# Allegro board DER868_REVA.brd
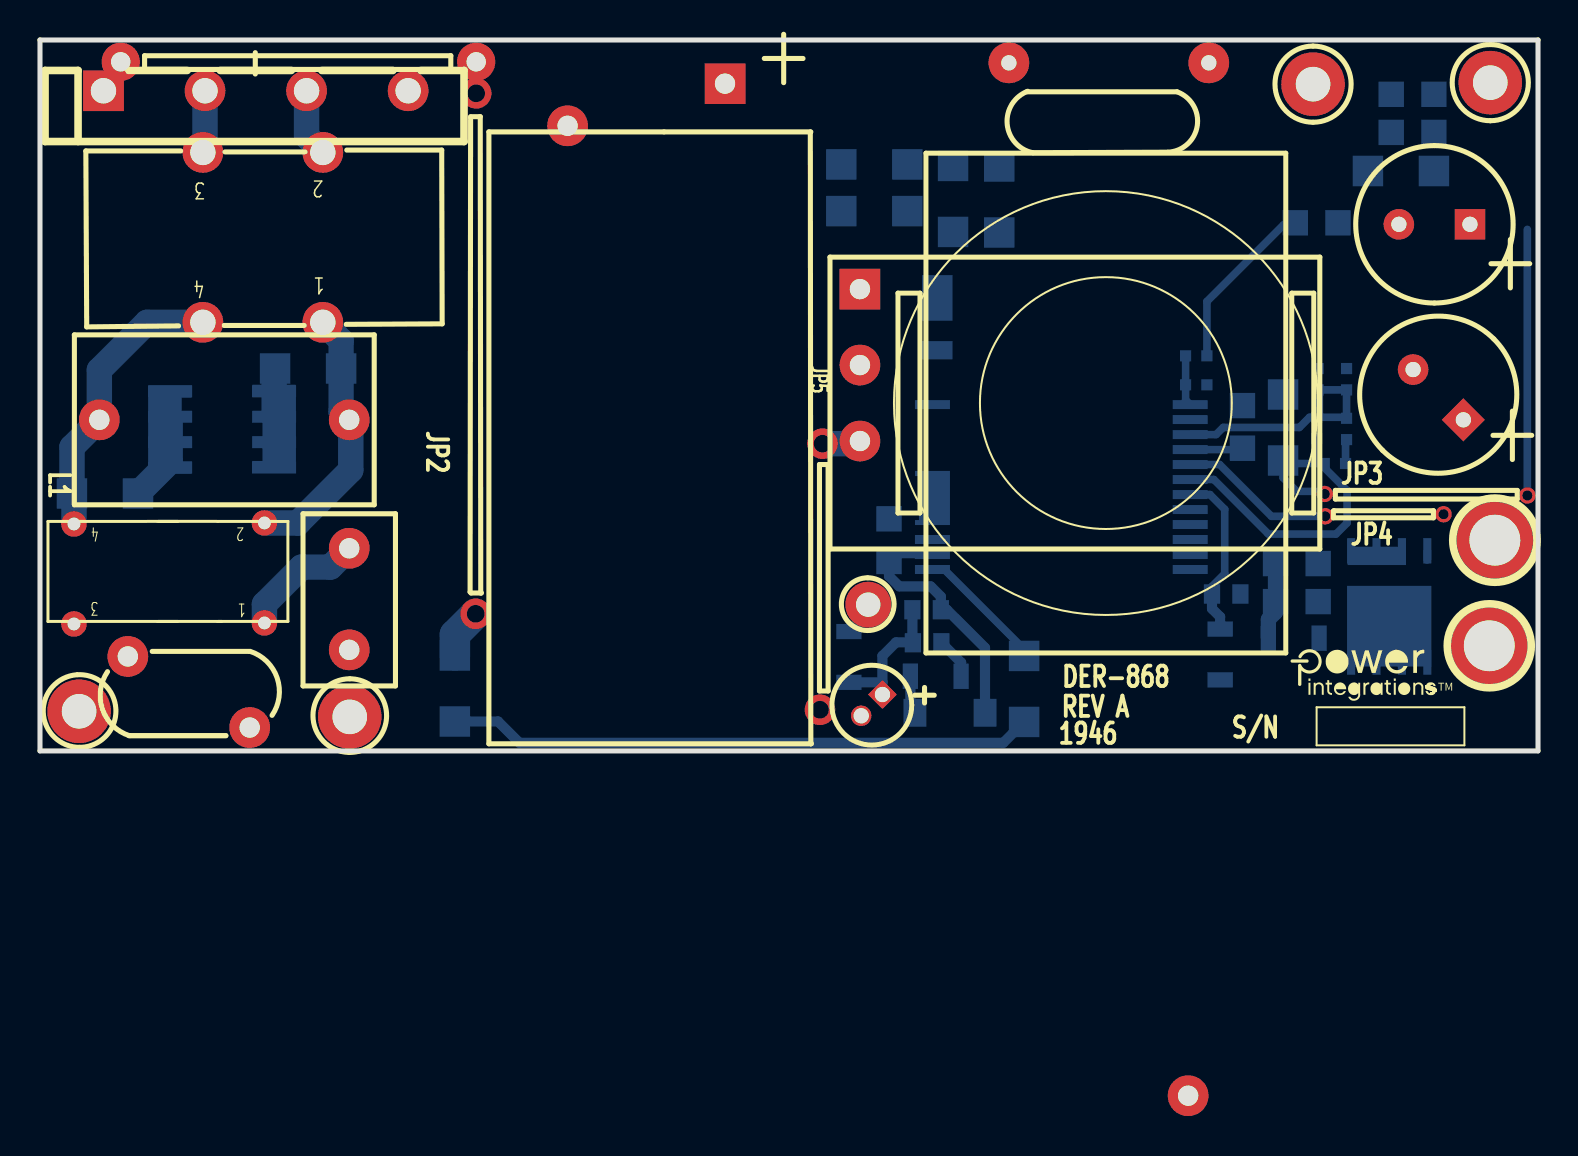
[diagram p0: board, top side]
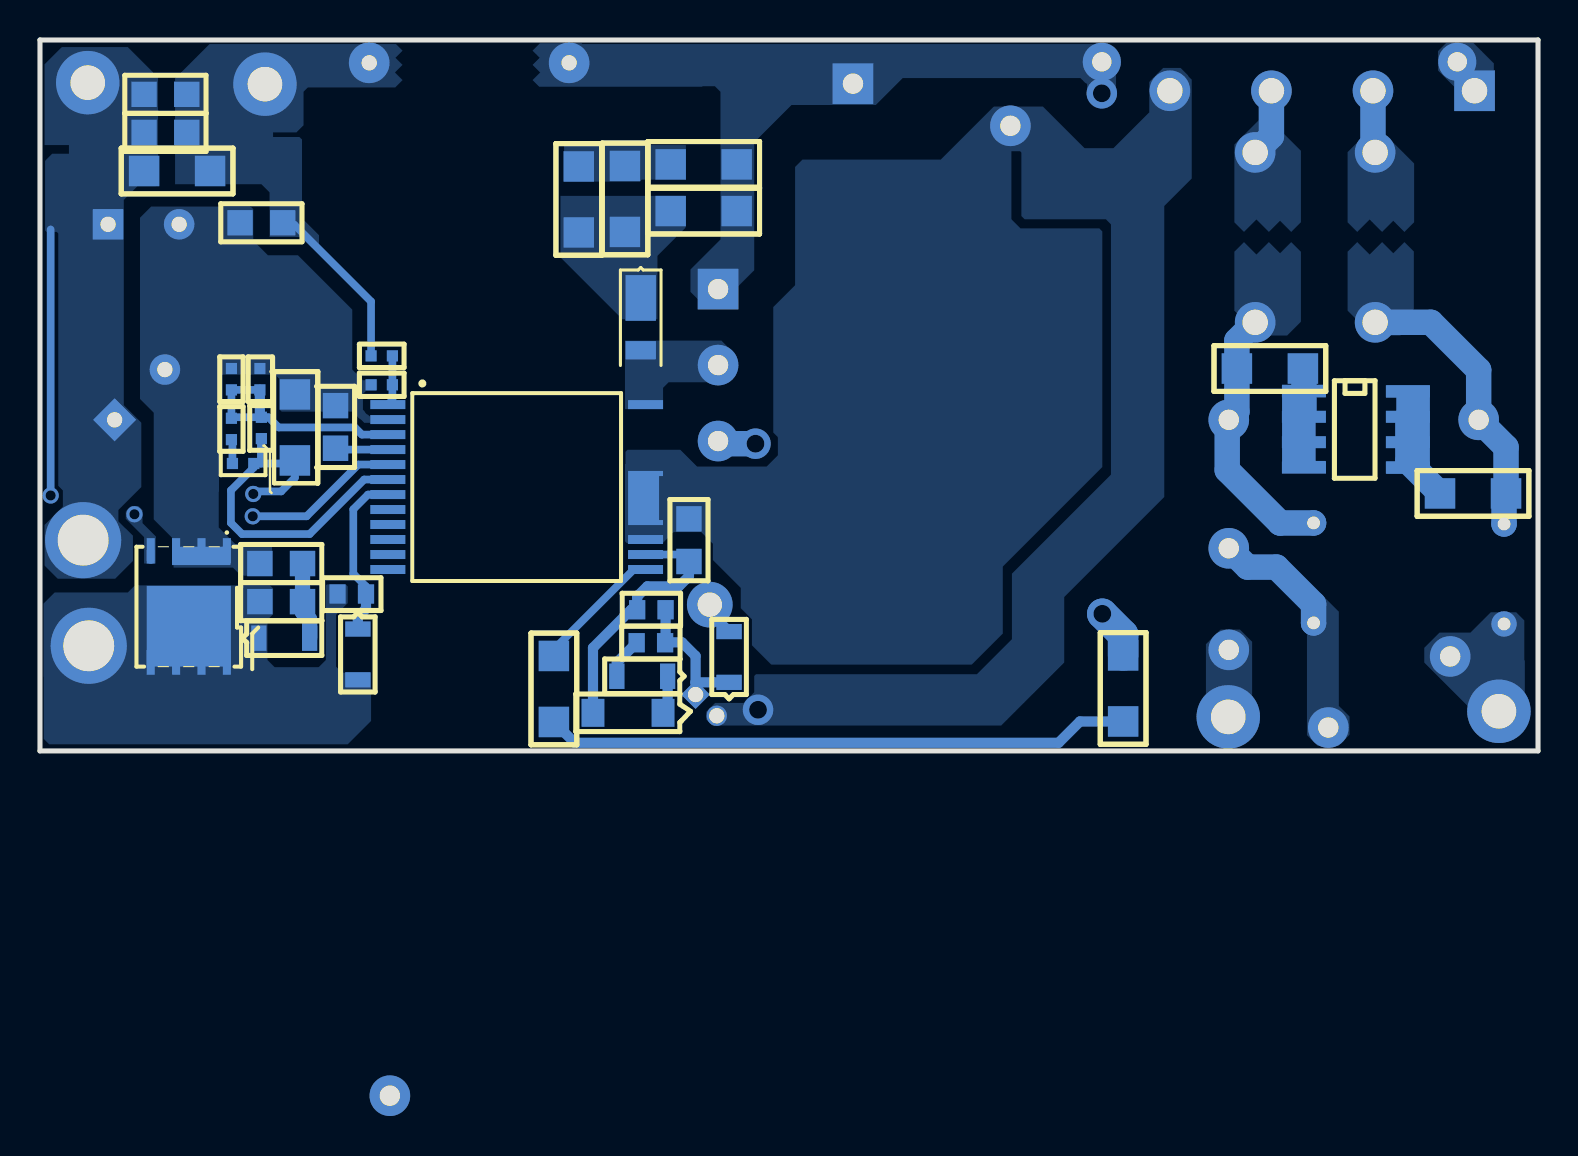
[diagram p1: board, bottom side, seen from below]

Outline 74.93 x 35.56 mm; copper layers: TOP, BOTTOM. Coordinates in mm from the lower left corner of the outline.
Outline path: 0,35.56 74.93,35.56 74.93,0 0,0 0,35.56

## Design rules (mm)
constraint set DEFAULT: min track width 0.508

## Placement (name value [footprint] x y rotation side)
BR1  GBL06  [PIDAXBRIDGEGBL06]  3.17 33.02 0 top
C1  330 nF  [PINP_XCAPRAD15X8P5X14HD040]  15.47 16.56 180 top
C2  100 uF  [PIPOLCAPCLYD630LS300040]  34.26 33.38 180 bottom
C3  680 pF  [PINPCAPRAD394X275394030]  48.46 34.42 0 top
C4  2.2 nF  [PISMC1206]  40.08 29.34 0 bottom
C5  6.8 uF  [PIPOLCAP4P0X11P0XLS1P5D030]  42.14 2.82 225 top
C6  4.7 uF  [PISMC0805]  42.47 9.47 90 bottom
C7  3.3 nF  [PISMC0805]  61.8 9.37 0 bottom
C8  560 uF  [PIPOLCAPCLYD320LS140030]  71.2 16.56 135 top
C9  560 uF  [PIPOLCAPCLYD320LS140030]  71.53 26.34 180 top
C10  2.2 uF  [PISMC0805]  60.15 17.27 270 bottom
C11  2.2 uF  [PISMC1206]  62.18 17.83 270 bottom
C12  1000 pF  [PISMR0402]  58.37 18.31 180 bottom
C13  330 pF  [PISMC0402]  63.93 18.06 90 bottom
C14  10 nF  [PISMR0402]  65.35 15.57 90 bottom
C15  47 uF  [PISMC1206]  69.72 29.01 180 bottom
C16  1 uF  [PISMC0805]  69.72 30.94 180 bottom
C17  DNP  [PISMC0805]  69.72 32.84 180 bottom
D1  DFLR1800-7  [PISMDDFLR120012]  44.88 22.68 90 bottom
D2  BAV3004WS-7  [PISMSOD323]  40.46 3.43 90 bottom
D3  BAV19WS  [PISMSOD323]  43.54 3.73 0 bottom
D4  BAV19WS  [PISMSOD323]  63.98 5.64 180 bottom
D5  BAV21WS-7-F  [PISMSOD323]  59.03 6.1 270 bottom
F1  3.15 A  [PI_RST_MICROFUSE]  15.47 5.05 90 top
FL1  Hole_100mils  [PI_HOLE_100MIL]  72.77 10.54 0 top
FL2  Hole_100mils  [PI_HOLE_100MIL]  72.49 5.26 0 top
FL3  Hole_50mils  [PI_HOLE_50MIL]  41.43 7.32 0 top
J1  PCB Terminal 18 AWG  [PI_HOLE_18AWG]  15.49 1.68 0 top
J2  PCB Terminal 18 AWG  [PI_HOLE_18AWG]  1.96 1.96 0 top
J3  PCB Terminal 18 AWG  [PI_HOLE_18AWG]  72.54 33.4 0 top
J4  PCB Terminal 18 AWG  [PI_HOLE_18AWG]  63.68 33.32 0 top
JP1  J  [PI_JUMPER700]  4.04 34.47 0 top
L1  250 uH  [PI_TOROID_CMC4P_V_275UH]  7.9 6.48 180 top
L2  04291-T231  [PI_CMC_18MH_SUMIDA]  14.15 21.44 180 top
NOREF  -  []  62 4.98 0 top
NOREF#2  -  []  -231.19 -144.73 0 top
NOREF#3  -  []  0 35.56 0 top
NOREF#4  -  []  -153.38 54.28 0 top
NOREF#5  -  []  0.03 0.03 90 top
Q1  AON6220  [PISMPQFN5X6B]  65.58 10.01 0 bottom
R1  1 M  [PISMR1206]  15.06 19.13 180 bottom
R2  1 M  [PISMR1206]  4.9 12.88 180 bottom
R3  2.00 M  [PISMR1206]  20.75 1.47 90 bottom
R4  1.80 M  [PISMR1206]  49.23 4.75 270 bottom
R5  39  [PISMR1206]  47.98 25.93 90 bottom
R6  39  [PISMR1206]  45.67 25.96 90 bottom
R7  300 k  [PISMR1206]  40.08 27 0 bottom
R8  3 k  [PISMR0603]  43.64 7.06 0 bottom
R9  47  [PISMR0603]  43.66 5.41 0 bottom
R11  3  [PISMR0805]  61.8 7.47 0 bottom
R12  47  [PISMR0603]  60.05 7.85 180 bottom
R13  0.0  [PISMR0402]  57.3 19.76 0 bottom
R14  0.006  [PISMR0805]  64.92 26.42 180 bottom
R15  169.0 k  [PISMR0402]  63.86 15.62 90 bottom
R16  19.1 k  [PISMR0402]  65.35 19.13 270 bottom
R17  82.0 k  [PISMR0402]  64.24 14.38 0 bottom
RV1  DNP  [PIDISC350X160LS210X140040]  10.49 1.17 180 top
T1  EQ25  [PI_BOBBIN_EQ-2515P5_4P]  53.31 17.4 0 top
U1  INN3679C-H606  [PI_IC_INSOP_24D]  57.53 17.32 180 bottom
U2  CAP200DG  [PI_IC_SMD_SO8_CAPZERO]  11.71 17.98 270 bottom
VR1  MMSZ5242B-7-F  [PI_SM_SOD-123_12]  43.76 1.91 0 bottom

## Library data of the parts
BR1 = DISCRETE BRIDGE_+~~-: room: 2
C1 = CAP NP: alternate symbols: (pinp_xcaprad15x8p5x14Hd040H); room: 2
C2 = CAP POL: alternate symbols: (pipolcapclyd630ls3000401120h); room: 2
C3 = CAP NP: alternate symbols: (pinpycaprad500x220ls400040); room: 2
C4 C10 = CAP NP_0: room: 2
C5 = CAP POL: alternate symbols: (pipolcap4p0x11p0xls1p5d030h); room: 2
C6 C7 C11 C14-C17 = CAP NP: room: 2
C8 C9 = CAP POL: alternate symbols: (pipolcapclyd320ls140030430h); room: 2
C12 C13 = CAP NP: alternate symbols: (pismr0402_1); room: 2
D1-D4 = DIODE: room: 2
D5 = DIODE
F1 = FUSE: alternate symbols: (pirstmicrofusehoz); room: 2
FL1-FL3 = FlyingLead: room: 2
J1-J4 = TERM_1Pin: room: 2
JP1 = JUMPER_1: room: 2
L1 = TORRID 4P_12_34: alternate symbols: (pi_toroid_CMC4p_V,pi_toroid_CMC4p_V_275uH); room: 2
L2 = TORRID 4P_12_43a: room: 2
Q1 = FET_N_SGD_123_4_5678: room: 2
R1-R9 R11-R13 R15-R17 = R: room: 2
R14 = R
RV1 = VARISTOR: alternate symbols: (pi_disc_354x220_ls220x10_040_h); room: 2
T1 = BEQ2506_4P
U1 = Inno3EP_0
U2 = CAPZero: room: 2
VR1 = DIODE_ZENER: room: 2

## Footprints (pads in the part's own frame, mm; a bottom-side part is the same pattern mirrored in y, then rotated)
PI_BOBBIN_EQ-2515P5_4P
  rect 2.032x2.032 hole 1.016: 1(-12.301,5.7)
  round 2.032 hole 1.016: 2(-12.301,1.9) 3(-12.301,-1.9) 4(4.115,-34.646)
PI_CMC_18MH_SUMIDA
  round 2.032 hole 1.27: 1(0,0) 2(0,-8.499) 3(5.999,-8.499) 4(5.999,0)
PI_HOLE_18AWG
  round 3.175 hole 1.727: 1(0,0.025)
PI_HOLE_50MIL
  round 2.286 hole 1.219: 1(0,0)
PI_HOLE_100MIL
  round 3.81 hole 2.54: 1(0,0)
PI_IC_INSOP_24D
  rect 1.75x0.45 smd: 1(0,0) 2(0,-0.749) 3(0,-1.501) 4(0,-2.25) 5(0,-3) 6(0,-3.749) 7(0,-4.501) 8(0,-5.25) 9(0,-5.999) 10(0,-6.749) 11(0,-7.501) 12(0,-8.25) 13(12.89,-8.25) 14(12.89,-7.501) 15(12.89,-6.749) 24(12.89,0)
  custom 0.437x0.437 smd: 16(12.89,-4.671)
PI_IC_SMD_SO8_CAPZERO
  rect 0.599x2.2 smd: 1(0,0) 2(1.27,0) 3(2.54,0) 4(3.81,0) 5(3.81,5.199) 6(2.54,5.199) 7(1.27,5.199) 8(0,5.199)
PI_JUMPER700
  round 1.905 hole 0.965: 1(0,0) 2(17.78,0)
PI_RST_MICROFUSE
  round 2.032 hole 1.016: 1(0,0) 2(5.08,0)
PI_SM_SOD-123_12
  rect 1.143x1.397 smd: 1(0,0) 2(3.505,0)
PI_TOROID_CMC4P_V_275UH
  round 1.27 hole 0.635: 1(-3.327,0.076) 2(-3.327,-4.925) 3(6.2,0.127) 4(6.2,-4.874)
PIDAXBRIDGEGBL06
  rect 2.032x2.032 hole 1.27: 1(0,0)
  round 2.032 hole 1.27: 2(5.08,0) 3(10.16,0) 4(15.24,0)
PIDISC350X160LS210X140040
  round 2.032 hole 1.016: 1(0,0) 2(6.096,-3.556)
PINP_XCAPRAD15X8P5X14HD040
  round 2.032 hole 1.016: 1(0,0) 2(12.499,0)
PINPCAPRAD394X275394030
  round 2.032 hole 0.762: 1(0,0) 2(10,0)
PIPOLCAP4P0X11P0XLS1P5D030
  rect 1.016x1.016 hole 0.762: 1(0,0)
  round 1.016 hole 0.762: 2(1.501,0)
PIPOLCAPCLYD320LS140030
  rect 1.524x1.524 hole 0.762: 1(0,0)
  round 1.524 hole 0.762: 2(3.556,0)
PIPOLCAPCLYD630LS300040
  rect 2.032x2.032 hole 1.016: 1(0,0)
  round 2.032 hole 1.016: 2(7.874,-2.108)
PISMC0402
  rect 0.559x0.559 smd: 1(0,0) 2(1.067,0)
PISMC0805
  rect 1.27x1.27 smd: 1(0,0) 2(2.134,0)
PISMC1206
  rect 1.524x1.524 smd: 1(0,0) 2(3.302,0)
PISMDDFLR120012
  rect 2.286x1.524 smd: 1(-0.025,0)
  rect 0.914x1.524 smd: 2(-2.642,0)
PISMPQFN5X6B
  rect 0.406x1.27 smd: 1(0,0) 2(1.27,0) 3(2.54,0) 4(3.81,0)
  rect 0.406x1.219 smd: 5(3.81,5.588) 6(2.54,5.588) 7(1.27,5.588) 8(0,5.588)
PISMR0402
  rect 0.559x0.559 smd: 1(0,0) 2(1.067,0)
PISMR0603
  rect 0.813x0.965 smd: 1(0,0) 2(1.422,0)
PISMR0805
  rect 1.27x1.27 smd: 1(0,0) 2(2.134,0)
PISMR1206
  rect 1.524x1.524 smd: 1(0,0) 2(3.302,0)
PISMSOD323
  rect 0.762x1.27 smd: 1(0,0) 2(2.54,0)

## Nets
GND: C7.2 C8.2 C9.2 C10.1 C11.1 C12.1 C13.2 Q1.1 Q1.2 Q1.3(S3) R14.1 R16.1 U1.2
GND_SIGNAL: C3.2 C15.2 C16.2 C17.2 J4.1 R13.2 R14.2
VBUS_IN: C8.1 C9.1 C11.2 C15.1 C16.1 C17.1 FL1.1 J3.1 R15.1 R17.1 U1.6
D: D4.1 D5.2 FL2.1 Q1.5 Q1.6 Q1.7 Q1.8 R11.2 R12.1
NC8: U1.8
NC9: U1.9
NC10: U1.10
NC11: U1.11
NC12: U1.12
V-PIN: R4.1 U1.13(VPIN)
N10479111: F1.1 J1.1
N10805923: BR1.4 C2.2 C5.2 C6.2 T1.3 U1.15 U1.16
N10806149: C6.1 R8.2 U1.14 VR1.2
N10808843: C12.2 R13.1 U1.1
N10809540: Q1.4 U1.5
N10813018: R3.1 R4.2
N10840366: C2.1 C3.1 C4.1 JP1.2 R3.2 R7.1 T1.1
N10873526: D5.1 R12.2 U1.7
N10897256: C13.1 C14.2 R15.2 R16.2 U1.3
N10950053: C5.1 D2.1 R8.1 R9.1
N10966650: D1.2 T1.2 U1.24
N11058959: BR1.1 JP1.1
N11077448: D3.2 R9.2
N11099981: C1.1 L1.2 L2.1 R1.1
N11100013: C1.2 L1.4 L2.4 R2.2
N11100021: BR1.3(AC2) L2.2
N11100037: BR1.2 L2.3
N11105885: D2.2 FL3.1
N11139529: D1.1 R5.1 R6.1 R7.2
N11139619: C4.2 R5.2 R6.2
N11156493: C7.1 D4.2 R11.1
N11376588: F1.2 L1.1 RV1.1
N11376604: J2.1 L1.3 RV1.2
N11381159: R1.2 U2.2
N11473834: D3.1 VR1.1
N11479585: C14.1 R17.2
N11508957: R2.1 U2.7
N11512145: C10.2 U1.4

Pads without a net: T1 4; U2 1 3 4 5 6 8

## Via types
v1: diameter 1.524, hole 0.889, TOP to BOTTOM, 4 vias
v2: diameter 0.813, hole 0.508, TOP to BOTTOM, 4 vias

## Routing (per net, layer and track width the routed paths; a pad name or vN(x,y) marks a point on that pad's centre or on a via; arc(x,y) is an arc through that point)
GND: length 0.3
  BOTTOM w0.381: 59.99,17.35 60.07,17.27 C10.1 ; 63.96,9.35 C7.2 ; 62.15,17.81 C11.1
GND_SIGNAL: length 8.8
  BOTTOM w0.381: R14.2 62.69,26.31 62.2,26.31 58.37,22.48 R13.2
VBUS_IN: length 32.6
  BOTTOM w0.381: 63.88,14.38 62.33,14.38 C11.2 62.18,13.67 62.86,12.98 64.11,12.98 64.24,12.85 v2(64.26,12.85) ; 63.88,14.38 63.88,15.6 R15.1 ; 63.88,14.38 R17.1 64.24,14.17 65.38,13.03 65.38,11.4 64.82,10.85 61.44,10.85 58.71,13.57 U1.6 ; 74.4,26.09 v2(74.4,12.78)
V-PIN: length 6.6
  BOTTOM w0.381: R4.1 49.15,4.83 49.15,5.16 45.23,9.07 U1.13
N10805923: length 1.9
  BOTTOM w1.27: v1(39.14,15.37) 40.88,15.37 T1.3
  vias: v1(39.01,2.06)
N10806149: length 13
  BOTTOM w0.381: C6.1 42.82,9.82 U1.14
  BOTTOM w0.508: C6.1 42.47,8.74 42.98,8.23 44.55,8.23 45.06,7.72 R8.2 45.36,7.06 47.27,5.16 VR1.2
N10808843: length 2.5
  BOTTOM w0.381: R13.1 C12.2 57.3,17.55 U1.1
N10809540: length 8.3
  BOTTOM w0.381: 69.39,9.55 Q1.4 ; U1.5 59.01,14.32 61.59,11.73 v2(64.29,11.73)
  vias: v2(70.21,11.84)
N10813018: length 29.3
  BOTTOM w0.508: R3.1 22.91,1.47 23.98,0.41 48.18,0.41 R4.2
N10840366: length 2.5
  BOTTOM w1.524: R3.2 20.75,5.82 v1(21.79,6.86)
  vias: v1(21.82,32.89)
N10873526: length 8.5
  BOTTOM w0.381: U1.7 58.52,12.82 59.26,12.09 59.26,8.86 58.62,8.23 R12.2
  BOTTOM w0.508: R12.2 58.62,7.11 59.03,6.71 D5.1
N10897256: length 12.5
  BOTTOM w0.381: C13.1 R16.2 C14.2 65.3,16.69 R15.2 63.5,16.69 62.99,16.18 59.18,16.18 58.83,15.82 U1.3
  BOTTOM w0.508: C13.1 63.93,16.76 R15.2
N10950053: length 7.1
  BOTTOM w0.508: R8.1 43.64,5.44 43.64,5.43 ; 43.64,5.43 42.82,5.43 42.14,4.75 42.14,3.43 ; 43.64,5.43 R9.1 ; 42.14,3.43 D2.1 ; 42.14,3.43 C5.1
N11077448: length 2.1
  BOTTOM w0.508: D3.2 46.08,4.42 R9.2
N11099981: length 13.4
  BOTTOM w1.27: L2.1 15.06,20.52 R1.1 15.06,16.97 C1.1 15.54,16.48 15.54,14.05 12.9,11.4 12.9,11.4 L1.2
N11100013: length 14.5
  BOTTOM w1.27: L1.4 1.7,12.78 R2.2 1.6,15.19 C1.2 2.97,19.05 5.36,21.44 L2.4
N11100021: length 3.4
  BOTTOM w1.27: L2.2 13.33,30.75 BR1.3
N11100037: length 3.1
  BOTTOM w1.27: BR1.2 8.25,30.04 L2.3
N11105885: length 2.2
  BOTTOM w0.508: 41.4,7.4 41.4,6.9 ; 41.4,6.9 41.43,6.93 FL3.1 ; 41.4,6.9 D2.2
N11156493: length 3.9
  BOTTOM w0.762: D4.2 61.44,6.58 61.8,6.93 R11.1 C7.1
N11376588: length 6.3
  BOTTOM w1.27: F1.2 14.53,9.19 13.08,9.19 11.23,7.34 L1.1
N11381159: length 2.4
  BOTTOM w1.27: U2.2 11.71,19.08 R1.2
N11473834: length 1.9
  BOTTOM w0.508: VR1.1 43.54,2.13 D3.1
N11479585: length 1.2
  BOTTOM w0.381: R17.2 65.3,15.52 C14.1
N11508957: length 4.5
  BOTTOM w1.27: R2.1 6.51,14.49 U2.7
N11512145: length 2.6
  BOTTOM w0.381: 60.15,15.14 60.08,15.07 U1.4

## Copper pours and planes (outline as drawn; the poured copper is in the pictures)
GND on BOTTOM (solid shape): 68.33,9.3 65.41,9.3 65.41,10.21 68.33,10.21
GND on BOTTOM: 65.16,10.35 65.99,11.18 65.99,12.95 65.98,12.97 65.98,18.68 65.84,18.82 63.17,18.82 62.94,18.59 62.94,17.07 62.84,16.97 59.26,16.97 59.26,16.92 58.75,16.41 56.72,16.41 56.67,16.46 56.67,16.64 56.77,16.74 58.45,16.74 58.78,17.07 58.78,17.86 58.6,18.03 58.57,18.01 58.14,18.01 58.06,18.08 58.06,18.52 58.09,18.54 58.78,18.54 59.31,19.08 59.31,22.07 62.03,24.79 63.53,24.79 64.26,25.53 64.26,27.1 64.39,27.23 69.37,27.23 69.93,26.67 69.93,17.6 69.24,16.92 69.24,11.58 68.25,10.59 68.25,9.17 65.28,9.17 64.87,8.76 63.32,8.76 63.32,10.33 63.35,10.35
GND_SIGNAL on BOTTOM: 57.12,35.36 66.45,35.36 68.12,33.68 68.17,33.68 68.17,28.35 63.86,28.35 63.45,27.94 63.45,25.7 61.85,25.7 61.34,25.2 60.97,25.2 60.97,25.79 61.82,26.64 61.82,30.58 61.95,30.71 63.27,30.71 63.27,30.94 62.1,30.94 61.75,31.29 61.75,32.97 61.53,33.19 57.16,33.19 56.79,33.55 57.18,33.93 56.79,34.32 57.15,34.67 56.79,35.03
VBUS_IN on BOTTOM: 70.05,28.24 69.14,28.24 69.02,28.36 69.02,33.69 70.54,35.2 73.84,35.2 74.7,34.34 74.7,30.3 73.48,30.3 73.48,29.87 74.32,29.87 74.68,29.51 74.68,26.04 74.6,25.96 74.09,25.96 74.02,25.88 74.02,13.26 73.79,13.03 73.79,12.22 74.7,11.3 74.7,9.27 74.04,8.61 71.17,8.61 70.28,9.5 70.28,10.77 70.64,11.13 70.65,11.13 71.01,11.48 71.01,12.05 69.86,13.2 69.86,16.42 70.74,17.3 70.74,27.56
D on BOTTOM (solid shape): 69.6,4.22 65.38,4.22 65.38,8.25 69.6,8.25
D on BOTTOM: 74.75,3.71 74.74,3.7 74.74,0.6 74.47,0.33 59.54,0.33 58.37,1.5 58.37,3.91 59.82,3.91 60.12,4.22 60.12,6.81 59.54,7.39 59.54,8.23 59.64,8.33 60.58,8.33 60.63,8.28 60.63,4.55 60.99,4.19 63.2,4.19 63.55,4.55 63.55,6.55 63.27,6.83 63.27,8.13 63.42,8.28 70.18,8.28 70.54,7.92 74.19,7.92 74.75,7.37
Net_73 on BOTTOM (solid shape): 7.59,17.68 7.09,17.68 7.09,14.48 7.59,14.48 7.59,13.87 5.41,13.87 5.41,18.29 7.59,18.29
Net_77 on BOTTOM (solid shape): 12.8,13.89 10.62,13.89 10.62,14.5 11.13,14.5 11.13,17.7 10.62,17.7 10.62,18.31 12.8,18.31
N10479111 on BOTTOM: 16.61,0.79 16.18,0.36 14.83,0.36 14.3,0.89 14.3,5.46 14.91,6.07 15.88,6.07 16.61,5.33
N10805923 on BOTTOM: 17.88,34.16 18.75,34.16 19.44,33.46 19.44,31.94 21.23,30.15 22.68,30.15 24.77,32.23 27.22,32.23 29.87,29.58 36.79,29.58 37.16,29.21 37.16,23.29 38.25,22.2 38.25,15.93 38.02,15.7 38.02,14.78 38.58,14.22 42.06,14.22 42.9,15.06 45.54,15.06 45.64,14.96 45.64,14.35 45.67,14.35 45.67,10.49 45.57,10.39 43.79,10.39 43.23,10.95 41.86,10.95 41.27,10.36 41.27,9.55 39.88,8.15 39.88,7.14 39.32,6.58 39.32,5.28 38.35,4.32 28.32,4.32 26.77,5.87 26.77,9.22 21.79,14.2 21.79,25.98 21.95,26.14 25.88,26.14 26.34,26.59 26.34,30 25.91,30 25.84,29.93 25.84,26.76 25.68,26.59 21.62,26.59 21.36,26.34 21.36,13.82 26.31,8.86 26.31,5.59 28.07,3.84 39.12,3.84 39.2,3.75 39.2,2.93 39.74,2.4 41.16,2.4 41.61,1.96 41.61,1.57 41.3,1.27 26.85,1.27 23.7,4.42 23.7,7.7 18.69,12.7 18.69,27.25 17.32,28.63 17.32,33.58 17.5,33.76 17.5,33.78
N10809540 on BOTTOM: 69.14,9.37 69.14,10.62 69.13,10.63 69.13,10.72 69.8,11.39 69.8,12.04 70,12.24 70.41,12.24 70.64,12.01 70.64,11.61 69.72,10.69 69.72,9.37
N10840366 on BOTTOM: 47.84,35.39 49.92,35.39 50.29,35.03 49.94,34.67 50.29,34.32 49.91,33.93 50.29,33.55 49.96,33.22 41.81,33.22 41.78,33.25 41.17,33.25 40.89,32.97 40.89,25.58 42.39,24.08 42.39,22.96 41.78,22.35 40.89,22.35 39.2,24.04 39.2,30.44 37.34,32.31 33.12,32.31 31.78,33.66 22.89,33.66 22.63,33.4 22.61,33.4 22.56,33.35 22.56,32.84 22.33,32.61 21.49,32.61 21.11,32.99 21.11,34.85 21.62,35.36 47.8,35.36
N10966650 on BOTTOM: 43.76,17.09 43.76,18.16 43.48,18.44 40.92,18.44 40.39,18.97 40.39,20.07 40.84,20.52 45.67,20.52 45.67,17.09
N11058959 on BOTTOM: 4.6,35.41 3.23,35.41 2.21,34.39 2.21,32.05 4.17,32.05 4.19,32.08 4.19,32.92 4.17,32.94 4.17,33.2 5,34.04 5,35
N11099981 on BOTTOM: 13.46,25.45 12.9,24.89 12.34,25.45 11.86,24.97 11.86,21.46 12.55,20.78 13.94,20.78 15.19,22.02 15.19,24.97 14.71,25.45 14.08,24.83
N11100013 on BOTTOM: 7.8,25.45 7.24,24.89 6.68,25.45 6.21,24.98 6.21,21.45 6.88,20.78 8.28,20.78 9.52,22.02 9.52,24.97 9.04,25.45 8.42,24.83
N11100021 on BOTTOM: 12.9,26.52 13.46,25.96 14.07,26.57 14.07,26.59 14.71,25.96 15.19,26.44 15.19,30.33 13.84,31.67 13.51,31.67 11.86,30.02 11.86,26.44 12.34,25.96
N11100037 on BOTTOM: 7.24,26.52 7.8,25.96 8.41,26.57 8.41,26.59 9.04,25.96 9.52,26.44 9.52,29.95 8.84,30.63 7.44,30.63 6.2,29.39 6.2,26.44 6.68,25.96
N11139529 on BOTTOM: 48.89,27.76 48.89,24.69 45.8,21.59 44.04,21.59 44.04,24.77 42.65,26.16 42.65,27.71 42.7,27.76
N11139619 on BOTTOM: 42.62,28.58 44.83,28.58 44.93,28.47 48.72,28.47 48.72,30.3 42.62,30.3
N11376588 on BOTTOM: 9.43,0.81 9.98,0.25 11.02,0.25 11.56,0.79 11.56,5.87 11.84,6.15 11.84,7.72 11.66,7.9 10.9,7.9 9.96,6.96 9.96,2.25 9.43,1.72
N11376604 on BOTTOM: 0.66,1.12 0.66,4.52 0.69,4.55 0.69,6.53 1.09,6.93 2.36,6.93 3.38,5.92 4.93,5.92 5.69,5.16 5.69,4.42 1.93,0.66 1.12,0.66

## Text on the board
Ref Des/Silkscreen Top: JP5 | 1946 | REV A | DER-868 | S/N | JP3 | JP4 | JP2
User.5: 14.  FAB HOUSE LOGO,DATE CODE TO BE IN SILK SCREEN ONLY.DO NOT USE COPPER. | 13.  MATERIAL FR4 COPPER 2oz THICKNESS 0.062" | PLEASE DELETE THESE PINS
User.8: FIGURE | FINISHED_SIZE | 20.0 | 25.0 | 30.0 | 35.0 | 38.0 | 40.0 | 48.0 | 50.0 | 68.0 | 100.0 | DRILL CHART: TOP to BOTTOM | ALL UNITS ARE IN MILS | TOLERANCE_DRILL | +0.0/-0.0 | +3.0/-3.0 | PLATED | QTY | 4 | 2 | 6 | 1 | 8
